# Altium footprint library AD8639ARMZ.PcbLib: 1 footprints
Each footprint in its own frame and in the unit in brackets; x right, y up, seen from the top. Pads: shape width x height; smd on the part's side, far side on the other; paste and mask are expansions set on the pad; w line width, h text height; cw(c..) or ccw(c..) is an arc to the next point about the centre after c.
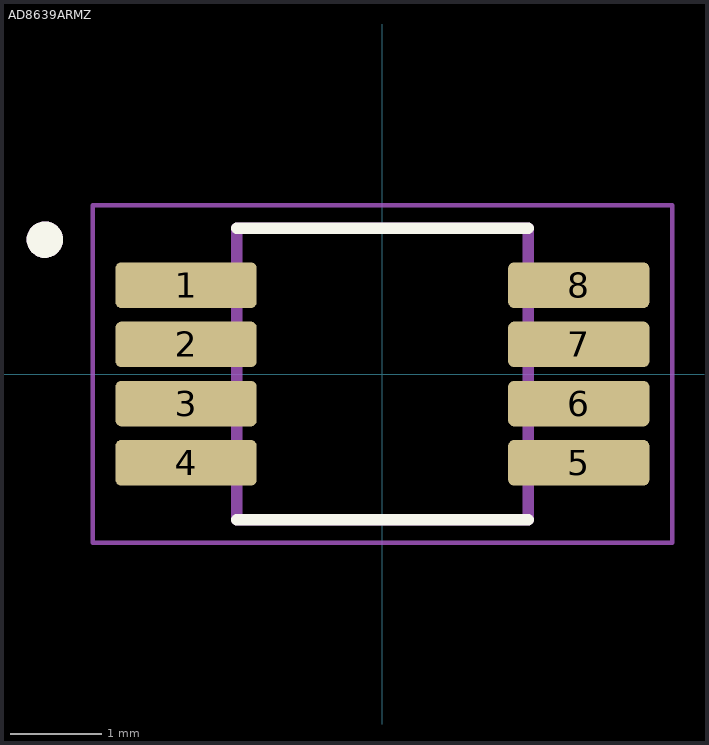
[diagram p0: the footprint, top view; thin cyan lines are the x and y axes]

## AD8639ARMZ [mm]
pads (8):
  rrect25% 1.55x0.5 smd: 1(-2.155,0.975) 2(-2.155,0.325) 3(-2.155,-0.325) 4(-2.155,-0.975) 5(2.155,-0.975) 6(2.155,-0.325) 7(2.155,0.325) 8(2.155,0.975)
Top Overlay:
  circle w0.2: c-3.705,1.475 r0.1
  lines w0.127: -1.6,-1.6 1.6,-1.6 ; -1.6,1.6 1.6,1.6
Mechanical 13:
  circle w0.2: c-3.705,1.475 r0.1
  lines w0.127: -1.6,-1.6 1.6,-1.6 1.6,1.6 -1.6,1.6 -1.6,-1.6
Mechanical 15:
  lines w0.05: -3.18,-1.85 3.18,-1.85 3.18,1.85 -3.18,1.85 -3.18,-1.85
3D body "step_temp.STEP": height 1.1, standoff 0, extent -2.45,-1.5 2.45,1.5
